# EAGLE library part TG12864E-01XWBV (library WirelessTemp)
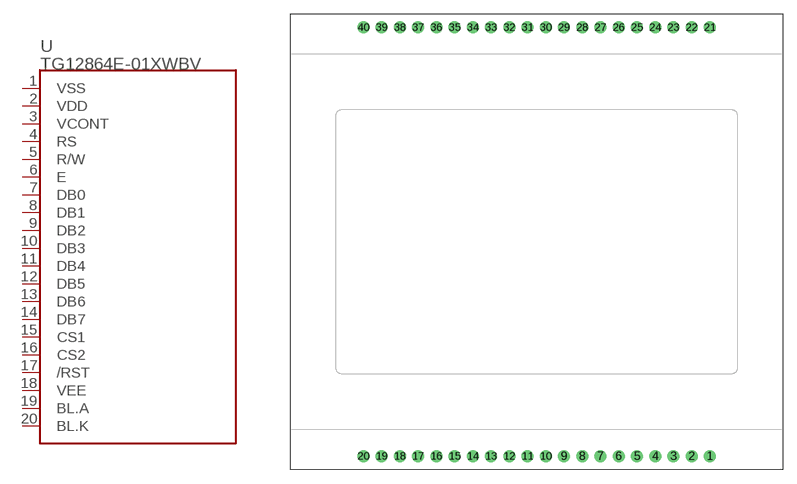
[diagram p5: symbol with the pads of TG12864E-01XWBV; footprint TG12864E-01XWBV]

Designator prefix U

## TG12864E-01XWBV  [TG12864E-01XWBV]
1  VSS  pwr
2  VDD  pwr
3  VCONT  in
4  RS  in
5  R/W  in
6  E  in
7  DB0
8  DB1
9  DB2
10  DB3
11  DB4
12  DB5
13  DB6
14  DB7
15  CS1  in
16  CS2  in
17  /RST  in
18  VEE  out
19  BL.A  pas
20  BL.K  pas

## Footprint TG12864E-01XWBV (pad centres in mm)
drill 0.8 round: 1 19,-23.5; 2 17,-23.5; 3 15,-23.5; 4 13,-23.5; 5 11,-23.5; 6 9,-23.5; 7 7,-23.5; 8 5,-23.5; 9 3,-23.5; 10 1,-23.5; 11 -1,-23.5; 12 -3,-23.5; 13 -5,-23.5; 14 -7,-23.5; 15 -9,-23.5; 16 -11,-23.5; 17 -13,-23.5; 18 -15,-23.5; 19 -17,-23.5; 20 -19,-23.5; 21 19,23.5; 22 17,23.5; 23 15,23.5; 24 13,23.5; 25 11,23.5; 26 9,23.5; 27 7,23.5; 28 5,23.5; 29 3,23.5; 30 1,23.5; 31 -1,23.5; 32 -3,23.5; 33 -5,23.5; 34 -7,23.5; 35 -9,23.5; 36 -11,23.5; 37 -13,23.5; 38 -15,23.5; 39 -17,23.5; 40 -19,23.5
